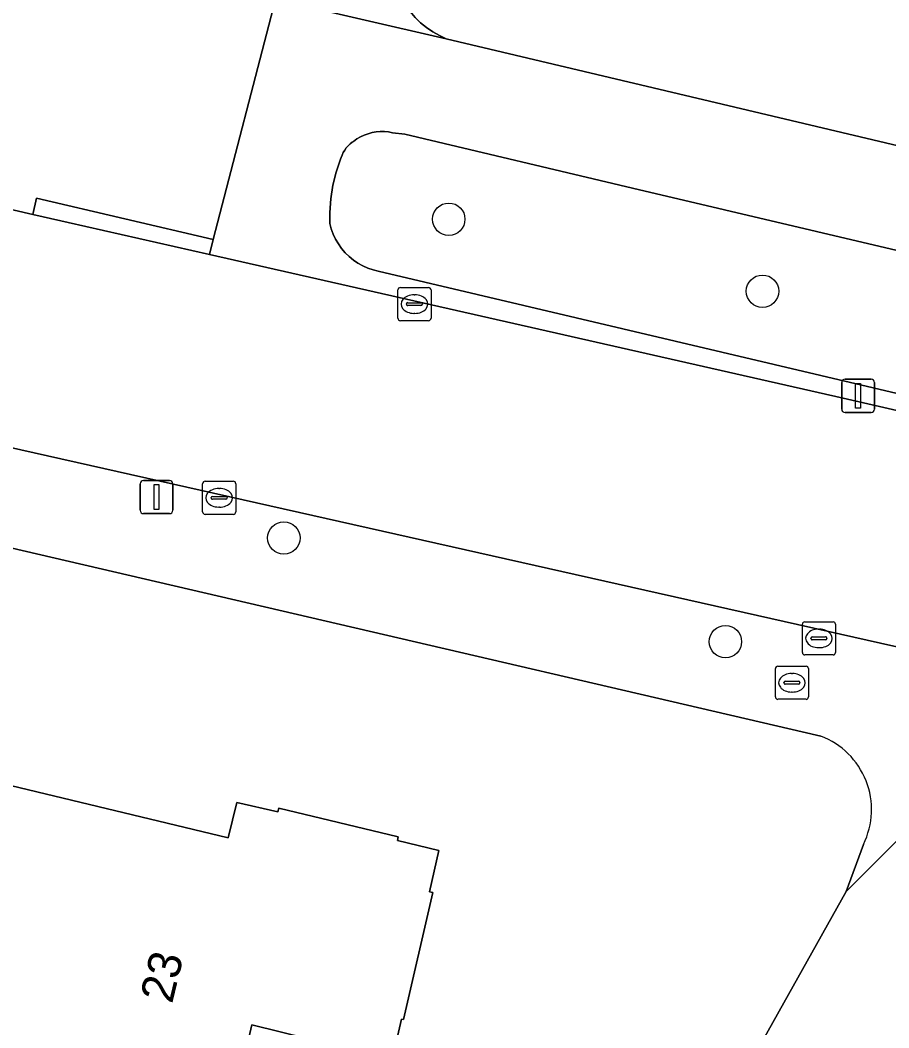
# Model space of a CAD drawing. Extents: x 162184 to 163154, y 385507 to 386516.
# Drawn here: x 162759.38 to 162785.59, y 385954.92 to 385985.31 of the extents above; entities that cross this region are included whole.
import ezdxf

# ---------------------------------------------------------------- set-up
doc = ezdxf.new("R2010")
doc.units = 0
for name, color, linetype in [('IMGEO_Boom', 7, 'Continuous'), ('IMGEO_Brandkraan', 7, 'Continuous'), ('IMGEO_Erf', 7, 'Continuous'), ('IMGEO_Groenvoorziening', 7, 'Continuous'), ('IMGEO_Kolk', 7, 'Continuous'), ('IMGEO_Lichtmast', 7, 'Continuous'), ('IMGEO_Pand', 7, 'Continuous'), ('IMGEO_Pand_nummerreeks', 7, 'Continuous'), ('IMGEO_Rijbaan_lokaal_open', 7, 'Continuous'), ('IMGEO_Voetpad_open', 7, 'Continuous')]:
    doc.layers.add(name, color=color, linetype=linetype)

msp = doc.modelspace()

# ---------------------------------------------------------------- linework, layer by layer
at = {"layer": 'IMGEO_Boom'}
for centre in [(162772.31, 385979.306), (162781.774, 385977.134), (162767.333, 385969.693), (162780.657, 385966.566)]:
    msp.add_circle(centre, 0.489, dxfattribs=at)
at = {"layer": 'IMGEO_Brandkraan'}
for p, q in [((162782.162, 385964.901), (162782.162, 385965.753)), ((162782.237, 385965.827), (162783.089, 385965.827)), ((162783.163, 385965.753), (162783.163, 385964.901)), ((162782.65, 385965.607), (162782.675, 385965.607)), ((162782.421, 385965.321), (162782.421, 385965.333)), ((162782.859, 385965.284), (162782.461, 385965.284)), ((162782.464, 385965.37), (162782.862, 385965.37)), ((162782.905, 385965.333), (162782.905, 385965.321)), ((162783.089, 385964.827), (162782.237, 385964.827)), ((162782.673, 385965.047), (162782.648, 385965.047))]:
    msp.add_line(p, q, dxfattribs=at)
for points in [[(162782.162, 385964.901), (162782.162, 385965.753)], [(162782.237, 385965.827), (162783.089, 385965.827)], [(162783.163, 385965.753), (162783.163, 385964.901)], [(162783.089, 385964.827), (162782.237, 385964.827)]]:
    msp.add_lwpolyline(points, dxfattribs=at)
for centre, radius, start, end in [((162782.239, 385965.751), 0.0765, 91.552, 178.448), ((162782.239, 385965.751), 0.0765, 91.552, 178.448), ((162783.087, 385965.751), 0.0765, 1.552, 88.448), ((162783.087, 385965.751), 0.0765, 1.552, 88.448), ((162782.461, 385965.33), 0.0403, 85.8775, 175.7526), ((162782.458, 385965.32), 0.0366, 178.938, 274.7102), ((162782.862, 385965.327), 0.043, 264.8664, 352.4533), ((162782.866, 385965.332), 0.0386, 1.7309, 96.639), ((162782.239, 385964.903), 0.0765, 181.552, 268.448), ((162782.239, 385964.903), 0.0765, 181.552, 268.448), ((162783.087, 385964.903), 0.0765, 271.552, 358.448), ((162783.087, 385964.903), 0.0765, 271.552, 358.448)]:
    msp.add_arc(centre, radius, start, end, dxfattribs=at)
for centre, major_axis, ratio, start_param, end_param in [((162782.649, 385965.327), (-0.387, 0.002), 0.722429, 4.712389, 7.853982), ((162782.674, 385965.327), (-0.39, 0.002), 0.717154, 1.570796, 4.712389)]:
    msp.add_ellipse(centre, major_axis=major_axis, ratio=ratio, start_param=start_param, end_param=end_param, dxfattribs=at)
at = {"layer": 'IMGEO_Erf'}
for points in [[(162783.536, 385963.718), (162627.446, 386000), (162549.733, 386018.064)], [(162779.843, 386017.945), (162774.431, 386000), (162770.7, 385987.627), (162770.667, 385986.603), (162770.725, 385986.381), (162770.803, 385986.164), (162770.9, 385985.956), (162771.015, 385985.757), (162771.147, 385985.569), (162771.296, 385985.393), (162771.459, 385985.232), (162771.637, 385985.086), (162771.827, 385984.956), (162772.027, 385984.844), (162772.235, 385984.751), (162794.574, 385979.46)], [(162751.92, 385954.712), (162752.324, 385956.394), (162747.762, 385957.491), (162745.102, 385958.131), (162746.556, 385964.179), (162749.215, 385963.54), (162749.443, 385964.489), (162754.068, 385963.285), (162754.102, 385963.426), (162765.654, 385960.65), (162765.911, 385961.719), (162767.152, 385961.43), (162767.179, 385961.542), (162770.787, 385960.683), (162770.76, 385960.567), (162772.007, 385960.271), (162771.729, 385959.026), (162771.825, 385959.002), (162770.94, 385955.166), (162770.882, 385955.18), (162770.6, 385953.963), (162766.368, 385955.013), (162765.564, 385951.507)], [(162753.719, 385904.451), (162756.813, 385909.97), (162784.294, 385959.028), (162784.82, 385960.452)]]:
    msp.add_lwpolyline(points, dxfattribs=at)
msp.add_arc((162782.692, 385961.501), 2.372, 333.7554, 69.1683, dxfattribs=at)
at = {"layer": 'IMGEO_Groenvoorziening'}
msp.add_lwpolyline([(162791.563, 385977.014), (162777.856, 385980.239), (162770.981, 385981.874), (162770.617, 385981.915), (162770.494, 385981.938), (162770.369, 385981.95), (162770.243, 385981.951), (162770.118, 385981.941), (162769.994, 385981.92), (162769.873, 385981.887), (162769.755, 385981.844), (162769.642, 385981.791), (162769.533, 385981.728), (162769.431, 385981.655), (162769.399, 385981.629), (162769.334, 385981.577), (162769.274, 385981.519), (162769.219, 385981.457), (162769.17, 385981.389), (162769.127, 385981.318), (162769.091, 385981.243), (162769.062, 385981.165), (162769.048, 385981.118), (162768.912, 385980.73), (162768.812, 385980.331), (162768.747, 385979.924), (162768.719, 385979.514), (162768.724, 385979.177), (162768.766, 385979.015), (162768.823, 385978.858), (162768.894, 385978.706), (162768.978, 385978.562), (162769.074, 385978.425), (162769.182, 385978.298), (162769.301, 385978.18), (162769.431, 385978.074), (162769.569, 385977.98), (162769.715, 385977.898), (162769.867, 385977.83), (162770.026, 385977.776), (162770.179, 385977.738), (162789.51, 385973.188)], dxfattribs=at)
at = {"layer": 'IMGEO_Kolk'}
for p, q in [((162770.774, 385976.321), (162770.774, 385977.173)), ((162770.849, 385977.247), (162771.701, 385977.247)), ((162771.262, 385977.027), (162771.287, 385977.027)), ((162771.775, 385977.173), (162771.775, 385976.321)), ((162771.033, 385976.741), (162771.033, 385976.753)), ((162771.471, 385976.704), (162771.073, 385976.704)), ((162771.076, 385976.79), (162771.474, 385976.79)), ((162771.517, 385976.753), (162771.517, 385976.741)), ((162771.285, 385976.467), (162771.26, 385976.467)), ((162771.701, 385976.247), (162770.849, 385976.247)), ((162764.882, 385970.479), (162764.882, 385971.331)), ((162764.957, 385971.405), (162765.809, 385971.405)), ((162765.37, 385971.185), (162765.395, 385971.185)), ((162765.883, 385971.331), (162765.883, 385970.479)), ((162765.141, 385970.899), (162765.141, 385970.911)), ((162765.184, 385970.948), (162765.582, 385970.948)), ((162765.625, 385970.911), (162765.625, 385970.899)), ((162765.579, 385970.862), (162765.181, 385970.862)), ((162765.393, 385970.625), (162765.368, 385970.625)), ((162765.809, 385970.405), (162764.957, 385970.405)), ((162782.977, 385966.239), (162782.977, 385967.091)), ((162783.052, 385967.165), (162783.904, 385967.165)), ((162783.465, 385966.945), (162783.49, 385966.945)), ((162783.978, 385967.091), (162783.978, 385966.239)), ((162783.236, 385966.659), (162783.236, 385966.671)), ((162783.279, 385966.708), (162783.677, 385966.708)), ((162783.72, 385966.671), (162783.72, 385966.659)), ((162783.674, 385966.622), (162783.276, 385966.622)), ((162783.488, 385966.385), (162783.463, 385966.385)), ((162783.904, 385966.165), (162783.052, 385966.165))]:
    msp.add_line(p, q, dxfattribs=at)
for points in [[(162770.774, 385976.321), (162770.774, 385977.173)], [(162770.849, 385977.247), (162771.701, 385977.247)], [(162771.775, 385977.173), (162771.775, 385976.321)], [(162771.701, 385976.247), (162770.849, 385976.247)], [(162764.882, 385970.479), (162764.882, 385971.331)], [(162764.957, 385971.405), (162765.809, 385971.405)], [(162765.883, 385971.331), (162765.883, 385970.479)], [(162765.809, 385970.405), (162764.957, 385970.405)], [(162782.977, 385966.239), (162782.977, 385967.091)], [(162783.052, 385967.165), (162783.904, 385967.165)], [(162783.978, 385967.091), (162783.978, 385966.239)], [(162783.904, 385966.165), (162783.052, 385966.165)]]:
    msp.add_lwpolyline(points, dxfattribs=at)
for centre, radius, start, end in [((162770.851, 385977.171), 0.0765, 91.552, 178.448), ((162770.851, 385977.171), 0.0765, 91.552, 178.448), ((162771.699, 385977.171), 0.0765, 1.552, 88.448), ((162771.699, 385977.171), 0.0765, 1.552, 88.448), ((162771.073, 385976.75), 0.0403, 85.8775, 175.7526), ((162771.07, 385976.74), 0.0366, 178.938, 274.7102), ((162771.474, 385976.747), 0.043, 264.8664, 352.4533), ((162771.478, 385976.752), 0.0386, 1.7309, 96.639), ((162770.851, 385976.323), 0.0765, 181.552, 268.448), ((162770.851, 385976.323), 0.0765, 181.552, 268.448), ((162771.699, 385976.323), 0.0765, 271.552, 358.448), ((162771.699, 385976.323), 0.0765, 271.552, 358.448), ((162764.959, 385971.329), 0.0765, 91.552, 178.448), ((162764.959, 385971.329), 0.0765, 91.552, 178.448), ((162765.807, 385971.329), 0.0765, 1.552, 88.448), ((162765.807, 385971.329), 0.0765, 1.552, 88.448), ((162765.181, 385970.908), 0.0403, 85.8775, 175.7526), ((162765.178, 385970.898), 0.0366, 178.938, 274.7102), ((162765.582, 385970.905), 0.043, 264.8664, 352.4533), ((162765.586, 385970.91), 0.0386, 1.7309, 96.639), ((162764.959, 385970.481), 0.0765, 181.552, 268.448), ((162764.959, 385970.481), 0.0765, 181.552, 268.448), ((162765.807, 385970.481), 0.0765, 271.552, 358.448), ((162765.807, 385970.481), 0.0765, 271.552, 358.448), ((162783.054, 385967.089), 0.0765, 91.552, 178.448), ((162783.054, 385967.089), 0.0765, 91.552, 178.448), ((162783.902, 385967.089), 0.0765, 1.552, 88.448), ((162783.902, 385967.089), 0.0765, 1.552, 88.448), ((162783.276, 385966.668), 0.0403, 85.8775, 175.7526), ((162783.273, 385966.658), 0.0366, 178.938, 274.7102), ((162783.677, 385966.665), 0.043, 264.8664, 352.4533), ((162783.681, 385966.67), 0.0386, 1.7309, 96.639), ((162783.054, 385966.241), 0.0765, 181.552, 268.448), ((162783.054, 385966.241), 0.0765, 181.552, 268.448), ((162783.902, 385966.241), 0.0765, 271.552, 358.448), ((162783.902, 385966.241), 0.0765, 271.552, 358.448)]:
    msp.add_arc(centre, radius, start, end, dxfattribs=at)
for centre, major_axis, ratio, start_param, end_param in [((162771.261, 385976.747), (-0.387, 0.002), 0.722429, 4.712389, 7.853982), ((162771.286, 385976.747), (-0.39, 0.002), 0.717154, 1.570796, 4.712389), ((162765.369, 385970.905), (-0.387, 0.002), 0.722429, 4.712389, 7.853982), ((162765.394, 385970.905), (-0.39, 0.002), 0.717154, 1.570796, 4.712389), ((162783.464, 385966.665), (-0.387, 0.002), 0.722429, 4.712389, 7.853982), ((162783.489, 385966.665), (-0.39, 0.002), 0.717154, 1.570796, 4.712389)]:
    msp.add_ellipse(centre, major_axis=major_axis, ratio=ratio, start_param=start_param, end_param=end_param, dxfattribs=at)
at = {"layer": 'IMGEO_Lichtmast'}
for p, q in [((162784.164, 385973.58), (162784.164, 385974.38)), ((162784.164, 385974.38), (162784.164, 385973.58)), ((162784.264, 385974.48), (162785.054, 385974.48)), ((162785.054, 385974.48), (162784.264, 385974.48)), ((162785.154, 385974.38), (162785.154, 385973.58)), ((162785.154, 385973.58), (162785.154, 385974.38)), ((162785.054, 385973.48), (162784.264, 385973.48)), ((162784.264, 385973.48), (162785.054, 385973.48)), ((162762.997, 385970.527), (162762.997, 385971.327)), ((162762.997, 385971.327), (162762.997, 385970.527)), ((162763.097, 385971.427), (162763.887, 385971.427)), ((162763.887, 385971.427), (162763.097, 385971.427)), ((162763.987, 385971.327), (162763.987, 385970.527)), ((162763.987, 385970.527), (162763.987, 385971.327)), ((162763.887, 385970.427), (162763.097, 385970.427)), ((162763.097, 385970.427), (162763.887, 385970.427))]:
    msp.add_line(p, q, dxfattribs=at)
for points in [[(162784.584, 385974.355), (162784.734, 385974.355), (162784.734, 385973.605), (162784.584, 385973.605), (162784.584, 385974.355)], [(162763.417, 385971.302), (162763.567, 385971.302), (162763.567, 385970.552), (162763.417, 385970.552), (162763.417, 385971.302)]]:
    msp.add_lwpolyline(points, dxfattribs=at)
for centre, start, end in [((162784.264, 385974.38), 90, 180), ((162784.264, 385974.38), 90, 180), ((162785.054, 385974.38), 0, 90), ((162785.054, 385974.38), 360, 90), ((162784.264, 385973.58), 180, 270), ((162784.264, 385973.58), 180, 270), ((162785.054, 385973.58), 270, 0), ((162785.054, 385973.58), 270, 0), ((162763.097, 385971.327), 90, 180), ((162763.097, 385971.327), 90, 180), ((162763.887, 385971.327), 0, 90), ((162763.887, 385971.327), 360, 90), ((162763.097, 385970.527), 180, 270), ((162763.097, 385970.527), 180, 270), ((162763.887, 385970.527), 270, 0), ((162763.887, 385970.527), 270, 0)]:
    msp.add_arc(centre, 0.1, start, end, dxfattribs=at)
at = {"layer": 'IMGEO_Pand'}
msp.add_lwpolyline([(162765.564, 385951.507), (162766.368, 385955.013), (162770.6, 385953.963), (162770.882, 385955.18), (162770.94, 385955.166), (162771.825, 385959.002), (162771.729, 385959.026), (162772.007, 385960.271), (162770.76, 385960.567), (162770.787, 385960.683), (162767.179, 385961.542), (162767.152, 385961.43), (162765.911, 385961.719), (162765.654, 385960.65), (162754.102, 385963.426), (162754.068, 385963.285), (162749.443, 385964.489), (162749.215, 385963.54), (162748.275, 385959.628), (162747.762, 385957.491), (162752.324, 385956.394), (162751.92, 385954.712)], dxfattribs=at)
at = {"layer": 'IMGEO_Rijbaan_lokaal_open'}
for points in [[(162765.095, 385978.24), (162759.758, 385979.448), (162757.068, 385980.076), (162720.741, 385988.554), (162719.147, 385981.746), (162727.339, 385979.826), (162730.448, 385979.097), (162742.931, 385976.169), (162746.702, 385975.285), (162751.636, 385974.128), (162755.187, 385973.295), (162786.628, 385966.226)], [(162791.867, 385972.147), (162784.207, 385973.914), (162765.095, 385978.24)]]:
    msp.add_lwpolyline(points, dxfattribs=at)
at = {"layer": 'IMGEO_Voetpad_open'}
for points in [[(162778.802, 386025.049), (162771.303, 386000), (162767.082, 385985.941), (162772.235, 385984.751), (162772.027, 385984.844), (162771.827, 385984.956), (162771.637, 385985.086), (162771.459, 385985.232), (162771.296, 385985.393), (162771.147, 385985.569), (162771.015, 385985.757), (162770.9, 385985.956), (162770.803, 385986.164), (162770.725, 385986.381), (162770.667, 385986.603), (162770.7, 385987.627), (162774.431, 386000), (162779.843, 386017.945), (162779.876, 386018.101), (162781.915, 386024.871)], [(162549.733, 386018.064), (162627.446, 386000), (162783.536, 385963.718)], [(162757.945, 385983.903), (162757.702, 385982.634), (162757.537, 385982.185), (162757.068, 385980.076), (162759.758, 385979.448), (162759.873, 385979.94), (162765.2, 385978.691), (162767.082, 385985.941), (162762.348, 385987.291), (162758.422, 385988.351), (162756.863, 385988.324), (162707.015, 386000), (162696.564, 386002.448), (162682.926, 386005.689), (162674.38, 386007.643), (162659.17, 386011.222)], [(162772.235, 385984.751), (162767.082, 385985.941), (162765.2, 385978.691), (162765.095, 385978.24), (162784.207, 385973.914), (162791.867, 385972.147)], [(162794.574, 385979.46), (162772.235, 385984.751)], [(162786.628, 385966.226), (162755.187, 385973.295), (162755.073, 385972.809), (162751.522, 385973.641), (162751.636, 385974.128), (162746.702, 385975.285), (162746.587, 385974.799), (162742.816, 385975.684), (162742.931, 385976.169), (162730.448, 385979.097), (162730.334, 385978.615), (162727.225, 385979.344), (162727.339, 385979.826), (162719.147, 385981.746), (162714.417, 385982.854), (162709.674, 385983.966)], [(162789.51, 385973.188), (162770.179, 385977.738), (162770.026, 385977.776), (162769.867, 385977.83), (162769.715, 385977.898), (162769.569, 385977.98), (162769.431, 385978.074), (162769.301, 385978.18), (162769.182, 385978.298), (162769.074, 385978.425), (162768.978, 385978.562), (162768.894, 385978.706), (162768.823, 385978.858), (162768.766, 385979.015), (162768.724, 385979.177), (162768.719, 385979.514), (162768.747, 385979.924), (162768.812, 385980.331), (162768.912, 385980.73), (162769.048, 385981.118), (162769.062, 385981.165), (162769.091, 385981.243), (162769.127, 385981.318), (162769.17, 385981.389), (162769.219, 385981.457), (162769.274, 385981.519), (162769.334, 385981.577), (162769.399, 385981.629), (162769.431, 385981.655), (162769.533, 385981.728), (162769.642, 385981.791), (162769.755, 385981.844), (162769.873, 385981.887), (162769.994, 385981.92), (162770.118, 385981.941), (162770.243, 385981.951), (162770.369, 385981.95), (162770.494, 385981.938), (162770.617, 385981.915), (162770.981, 385981.874), (162777.856, 385980.239), (162791.563, 385977.014)], [(162789.557, 385964.286), (162784.294, 385959.028), (162756.813, 385909.97), (162753.719, 385904.451), (162753.237, 385899.545)], [(162784.82, 385960.452), (162784.294, 385959.028), (162789.557, 385964.286)]]:
    msp.add_lwpolyline(points, dxfattribs=at)
msp.add_lwpolyline([(162759.758, 385979.448), (162765.095, 385978.24), (162765.2, 385978.691), (162759.873, 385979.94)], close=True, dxfattribs=at)
msp.add_arc((162782.692, 385961.501), 2.372, 333.7554, 69.1683, dxfattribs=at)

# ---------------------------------------------------------------- texts
at = {"layer": 'IMGEO_Pand_nummerreeks'}
msp.add_text('23', height=1, rotation=76.4899, dxfattribs=at).set_placement((162763.961, 385955.625))

doc.saveas('drawing.dxf')
